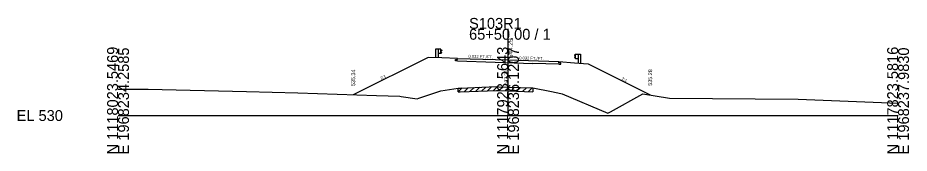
# Model space of a CAD drawing. Extents: x -26 to 203, y -10 to 12018.
# Drawn here: x -25.7 to 202.8, y 5990.3 to 6025.1 of the extents above; entities that cross this region are included whole.
import ezdxf

# ---------------------------------------------------------------- set-up
doc = ezdxf.new("R2010")
doc.units = 0
for name, color, linetype in [('Level 10', 7, 'Continuous'), ('Level 11', 7, 'Continuous'), ('Level 12', 7, 'Continuous'), ('Level 24', 7, 'Continuous'), ('Level 32', 7, 'Continuous'), ('Level 33', 7, 'Continuous'), ('Level 59', 7, 'Continuous'), ('Level 6', 7, 'Continuous'), ('Level 60', 7, 'Continuous'), ('Level 61', 7, 'Continuous'), ('Level 63', 7, 'Continuous'), ('Level 7', 7, 'Continuous')]:
    doc.layers.add(name, color=color, linetype=linetype)

msp = doc.modelspace()

# ---------------------------------------------------------------- linework, layer by layer
at = {"layer": 'Level 11'}
for p, q in [((86.5, 6014.4), (87, 6014.38)), ((86.5, 6014.04), (86.5, 6014.4)), ((87, 6014.02), (86.5, 6014.04)), ((87, 6014.38), (87, 6014.7)), ((113, 6013.56), (113, 6013.88)), ((113.5, 6013.55), (113, 6013.56)), ((113, 6013.2), (113.5, 6013.19)), ((113.5, 6013.19), (113.5, 6013.55))]:
    msp.add_line(p, q, dxfattribs=at)
at = {"layer": 'Level 12'}
for p in [(87, 6014.02), (113, 6013.2)]:
    msp.add_line(p, (106.39, 6013.41), dxfattribs=at)
at = {"layer": 'Level 24'}
for p, q in [((81.4, 6017.07), (81.4, 6014.87)), ((82.06, 6017.07), (81.4, 6017.07)), ((82.06, 6017.07), (82.06, 6014.85)), ((82.73, 6017.07), (82.06, 6017.07)), ((82.73, 6015.91), (82.06, 6015.91)), ((82.73, 6015.91), (82.73, 6017.07)), ((82.73, 6017), (83, 6016.8)), ((83, 6016.75), (82.73, 6016.55)), ((83, 6016.23), (82.73, 6016.43)), ((82.73, 6015.98), (83, 6016.18)), ((83, 6016.8), (83, 6016.75)), ((83, 6016.18), (83, 6016.23)), ((117.27, 6015.72), (117, 6015.52)), ((117, 6015.52), (117, 6015.47)), ((117, 6015.47), (117.27, 6015.27)), ((117, 6014.95), (117.27, 6015.15)), ((117.27, 6014.63), (117.27, 6015.79)), ((117.27, 6015.79), (117.94, 6015.79)), ((117.94, 6015.79), (117.94, 6013.46)), ((117.94, 6015.79), (118.6, 6015.79)), ((118.6, 6015.79), (118.6, 6013.41)), ((117, 6014.9), (117, 6014.95)), ((117.27, 6014.7), (117, 6014.9)), ((117.27, 6014.63), (117.94, 6014.63))]:
    msp.add_line(p, q, dxfattribs=at)
at = {"layer": 'Level 59'}
for p, q in [((87, 6014.7), (100, 6014.29)), ((100, 6014.29), (113, 6013.88))]:
    msp.add_line(p, q, dxfattribs=at)
at = {"layer": 'Level 6'}
for p, q in [((83, 6014.82), (79.5, 6014.93)), ((87, 6014.7), (83, 6014.82)), ((113, 6013.88), (117, 6013.54)), ((117, 6013.54), (120.5, 6013.25))]:
    msp.add_line(p, q, dxfattribs=at)
at = {"layer": 'Level 60'}
for p, q in [((0, 6006.8), (2.11, 6006.79)), ((2.11, 6006.79), (7.74, 6006.74)), ((7.74, 6006.74), (32.9, 6006.17)), ((32.9, 6006.17), (46.08, 6005.81)), ((77.09, 6004.5), (82.74, 6006.31)), ((82.74, 6006.31), (87.23, 6007.05)), ((87.23, 6007.05), (87.69, 6007.07)), ((87.69, 6007.07), (97.05, 6007.43)), ((97.05, 6007.43), (97.62, 6007.41)), ((97.62, 6007.41), (100, 6007.33)), ((100, 6007.33), (106.39, 6007.1)), ((106.39, 6007.1), (111.11, 6006.16)), ((111.11, 6006.16), (113.55, 6005.68)), ((46.08, 6005.81), (66.29, 6005.14)), ((66.29, 6005.14), (72.24, 6004.94)), ((72.24, 6004.94), (72.62, 6004.87)), ((72.62, 6004.87), (76.66, 6004.33)), ((76.66, 6004.33), (77.09, 6004.5)), ((113.55, 6005.68), (113.87, 6005.55)), ((113.87, 6005.55), (125.58, 6000.62)), ((126.27, 6000.99), (134.56, 6005.6)), ((134.56, 6005.6), (141.37, 6004.43)), ((141.37, 6004.43), (174.38, 6004.2)), ((174.38, 6004.2), (200, 6003.16)), ((125.58, 6000.62), (126.27, 6000.99))]:
    msp.add_line(p, q, dxfattribs=at)
at = {"layer": 'Level 61'}
for p, q in [((87.23, 6006.05), (88.27, 6007.09)), ((87.23, 6006.05), (87.23, 6007.05)), ((87.23, 6006.05), (87.69, 6006.07)), ((87.69, 6006.07), (97.05, 6006.43)), ((88.73, 6006.11), (89.77, 6007.15)), ((90.23, 6006.16), (91.27, 6007.21)), ((91.73, 6006.22), (92.77, 6007.26)), ((93.23, 6006.28), (94.27, 6007.32)), ((94.73, 6006.34), (95.77, 6007.38)), ((96.23, 6006.4), (97.25, 6007.42)), ((97.05, 6006.43), (97.62, 6006.41)), ((97.62, 6006.41), (100, 6006.33)), ((97.73, 6006.4), (98.69, 6007.37)), ((99.23, 6006.35), (100.19, 6007.32)), ((100, 6006.33), (106.39, 6006.1)), ((100.73, 6006.3), (101.69, 6007.27)), ((102.23, 6006.25), (103.19, 6007.21)), ((103.73, 6006.2), (104.69, 6007.16)), ((105.23, 6006.14), (106.19, 6007.11)), ((106.39, 6007.1), (106.39, 6006.1))]:
    msp.add_line(p, q, dxfattribs=at)
at = {"layer": 'Level 63'}
for p, q in [((100, 6000), (100, 6022.29)), ((0, 6000), (100, 6000)), ((100, 6000), (200, 6000))]:
    msp.add_line(p, q, dxfattribs=at)
at = {"layer": 'Level 7'}
for p, q in [((79.5, 6014.93), (60.3, 6005.34)), ((120.5, 6013.25), (136.44, 6005.28))]:
    msp.add_line(p, q, dxfattribs=at)

# ---------------------------------------------------------------- texts
at = {"layer": 'Level 10'}
msp.add_text(' 537.33', height=0.9, rotation=90, dxfattribs=at).set_placement((99.95, 6007.47))
at = {"layer": 'Level 32'}
for s, rotation, p in [('0.032 FT./FT.', 358.1901, (89.84, 6014.86)), ('0.032 FT./FT.', 358.1901, (102.84, 6014.45)), ('2:1', 26.5651, (67.5, 6009.22)), ('2:1', 333.4349, (129.04, 6009.26))]:
    msp.add_text(s, height=0.75, rotation=rotation, dxfattribs=at).set_placement(p)
at = {"layer": 'Level 33'}
for s, p in [('535.34', (60.8, 6007.59)), ('535.28', (136.94, 6007.67))]:
    msp.add_text(s, height=1, rotation=90, dxfattribs=at).set_placement(p)
at = {"layer": 'Level 59'}
msp.add_text(' 544.29', height=1.2, rotation=90, dxfattribs=at).set_placement((101.2, 6014.29))
at = {"layer": 'Level 63'}
for s, p in [('S103R1', (90, 6022.29)), ('65+50.00 / 1', (90, 6019.49)), ('EL 530', (-26, 5998.6))]:
    msp.add_text(s, height=2.8, dxfattribs=at).set_placement(p)
for s, p in [('N 1118023.5469', (0, 5990)), ('E 1968234.2585', (2.8, 5990)), ('N 1117923.5643', (100, 5990)), ('E 1968236.1207', (102.8, 5990)), ('N 1117823.5816', (200, 5990)), ('E 1968237.9830', (202.8, 5990))]:
    msp.add_text(s, height=2.8, rotation=90, dxfattribs=at).set_placement(p)

doc.saveas('drawing.dxf')
